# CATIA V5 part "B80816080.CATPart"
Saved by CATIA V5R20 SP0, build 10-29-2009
Part number: B80816080
Revision: 4
Definition: design
Nomenclature: B80816080
Source: made
Description: NOT SPECIFIED
Bounding box of the stored display mesh (mm): x -10 to 10, y -10 to 10, z 0 to 80
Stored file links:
  C:\Users\Raffaele\Desktop\3D X SITO CF\BOLEX\4-PILLAR REF 808\B80816080.CATPart
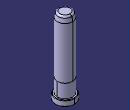
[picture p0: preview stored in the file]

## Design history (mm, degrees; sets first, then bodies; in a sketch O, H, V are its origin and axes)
Body1 "MANIFOLD_SOLID_BREP #450" (main body)
  Solid1: solid without history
